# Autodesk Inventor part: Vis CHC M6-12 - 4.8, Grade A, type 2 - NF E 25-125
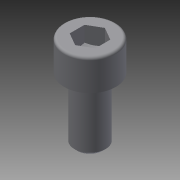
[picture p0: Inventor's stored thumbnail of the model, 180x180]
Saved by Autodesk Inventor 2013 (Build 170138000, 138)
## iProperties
Created: 2012-12
Part Number: Vis CHC M6-12 - 4.8, Grade A, type 2 - NF E 25-125
Material: Générique
Document SubType Name: Modeling
Designer: jost thierry
Density: 1 g/cm^3
Author: Régis FROMENT
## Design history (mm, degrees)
node "Vis CHC M6-12 - 4.8, Grade A, type 2 - NF E 25-1251"
node "Vis CHC M6-12 - 4.8, Grade A, type 2 - NF E 25-125"
node "Base1"
